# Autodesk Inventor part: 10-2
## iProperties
Author: Administrator
Created: 2001-02
Part Number: 10-2
Document SubType Name: Modeling
Designer: Administrator
Control State: 0
Master: False
Checked Out: False
PropertySet Name: Design Tracking Control
Shininess: 20.0
PropertySet Name: _Private Model Information
Density: 0.0
Volumn: 0.0
Area: 0.0
PropertySet Name: Model Information
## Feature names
1. Extrusion1
2. Extrusion2
3. Extrusion3
4. Extrusion4
5. Extrusion5
6. Hole1
7. Hole2
